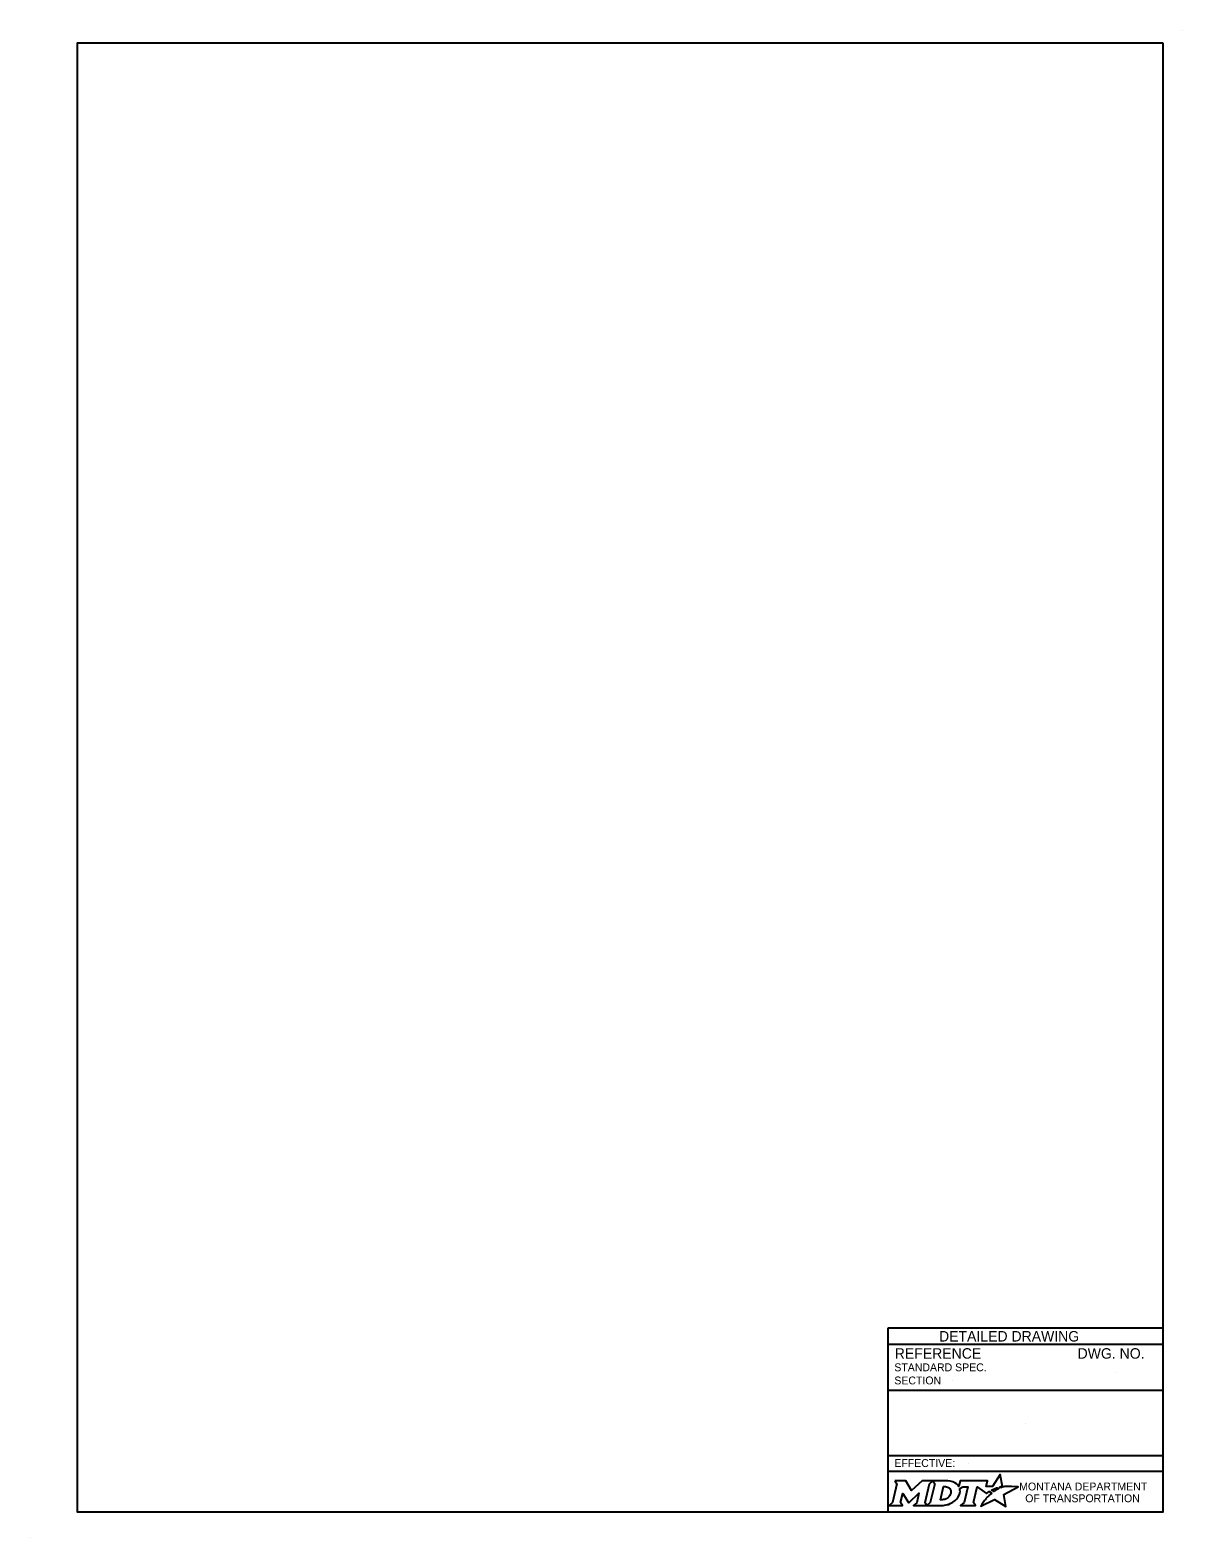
# Model space of a CAD drawing. Extents: x 49991.4 to 50021, y 49987.6 to 50011.4.
# Drawn here: x 49999.98 to 50008.76, y 49999.86 to 50011.36 of the extents above; entities that cross this region are included whole.
import ezdxf

# ---------------------------------------------------------------- set-up
doc = ezdxf.new("R2010")
doc.units = 0
doc.layers.add('Level 1', color=7, linetype='Continuous')
doc.layers.add('Level 2', color=7, linetype='Continuous')

msp = doc.modelspace()

# ---------------------------------------------------------------- linework, layer by layer
at = {"layer": 'Level 1'}
for p, q in [((50008.765, 50011.363), (50008.765, 50011.363)), ((49999.977, 49999.862), (49999.977, 49999.862))]:
    msp.add_line(p, q, dxfattribs=at)
msp.add_lwpolyline([(50008.615, 50011.263), (50000.336, 50011.263), (50000.336, 50000.062), (50008.615, 50000.062)], close=True, dxfattribs=at)
at = {"layer": 'Level 2'}
for p, q in [((50008.615, 50001.462), (50006.515, 50001.462)), ((50006.515, 50001.462), (50006.515, 50000.062)), ((50008.615, 50001.337), (50006.515, 50001.337)), ((50008.251, 50001.122), (50008.251, 50001.122)), ((50008.615, 50000.987), (50006.515, 50000.987)), ((50007.009, 50001.063), (50007.009, 50001.063)), ((50007.565, 50000.738), (50007.565, 50000.738)), ((50008.615, 50000.489), (50006.515, 50000.489)), ((50007.13, 50000.433), (50007.13, 50000.433)), ((50008.615, 50000.369), (50006.515, 50000.369))]:
    msp.add_line(p, q, dxfattribs=at)
for points in [[(50006.57, 50000.297), (50006.584, 50000.274), (50006.551, 50000.131), (50006.525, 50000.108), (50006.627, 50000.108), (50006.613, 50000.131), (50006.629, 50000.201), (50006.673, 50000.132), (50006.678, 50000.132), (50006.753, 50000.202), (50006.737, 50000.13), (50006.712, 50000.108), (50006.814, 50000.108), (50006.8, 50000.132), (50006.833, 50000.274)], [(50006.833, 50000.274), (50006.859, 50000.297), (50006.776, 50000.297), (50006.697, 50000.224), (50006.652, 50000.297), (50006.57, 50000.297)], [(50006.972, 50000.297), (50006.859, 50000.297), (50006.873, 50000.275), (50006.839, 50000.131), (50006.814, 50000.108), (50006.925, 50000.108)], [(50007.377, 50000.245), (50007.367, 50000.25), (50007.378, 50000.253), (50007.39, 50000.255), (50007.373, 50000.345), (50007.313, 50000.254), (50007.266, 50000.253), (50007.276, 50000.297), (50007.067, 50000.297), (50007.057, 50000.255), (50007.051, 50000.263)], [(50006.996, 50000.211), (50006.995, 50000.203), (50006.992, 50000.193), (50006.988, 50000.185), (50006.982, 50000.178), (50006.976, 50000.171), (50006.968, 50000.164), (50006.959, 50000.16), (50006.95, 50000.156), (50006.941, 50000.154), (50006.932, 50000.153), (50006.916, 50000.153), (50006.94, 50000.253), (50006.956, 50000.253), (50006.963, 50000.252), (50006.971, 50000.25), (50006.977, 50000.247), (50006.983, 50000.243), (50006.988, 50000.238), (50006.992, 50000.232), (50006.995, 50000.226), (50006.996, 50000.218), (50006.996, 50000.215), (50006.996, 50000.211)], [(50007.064, 50000.238), (50007.088, 50000.251), (50007.125, 50000.251), (50007.097, 50000.131), (50007.069, 50000.108), (50007.185, 50000.108), (50007.168, 50000.131), (50007.196, 50000.251), (50007.268, 50000.2), (50007.289, 50000.215), (50007.309, 50000.204)], [(50007.253, 50000.148), (50007.237, 50000.124), (50007.233, 50000.116), (50007.227, 50000.107), (50007.225, 50000.103), (50007.33, 50000.156), (50007.414, 50000.101), (50007.401, 50000.194), (50007.508, 50000.252), (50007.458, 50000.253), (50007.428, 50000.253), (50007.407, 50000.254), (50007.401, 50000.252), (50007.396, 50000.251), (50007.387, 50000.249), (50007.377, 50000.245)], [(50007.327, 50000.217), (50007.324, 50000.215), (50007.306, 50000.225), (50007.316, 50000.231), (50007.32, 50000.233), (50007.329, 50000.237), (50007.335, 50000.239), (50007.343, 50000.243), (50007.35, 50000.245), (50007.362, 50000.238), (50007.358, 50000.236), (50007.353, 50000.233), (50007.349, 50000.231), (50007.344, 50000.228), (50007.342, 50000.227), (50007.339, 50000.225), (50007.337, 50000.224), (50007.334, 50000.222), (50007.332, 50000.221), (50007.329, 50000.219), (50007.327, 50000.217)], [(50006.97, 50000.116), (50006.979, 50000.118), (50006.992, 50000.124), (50007.012, 50000.135)], [(50007.267, 50000.164), (50007.267, 50000.164)]]:
    msp.add_lwpolyline(points, dxfattribs=at)
for centre, radius, start, end in [((50006.951, 50000.236), 0.118, 300.9103, 339.1383), ((50006.995, 50000.219), 0.0709, 339.5329, 15.8582)]:
    msp.add_arc(centre, radius, start, end, dxfattribs=at)
for centre, major_axis, ratio, start_param, end_param in [((50006.97, 50000.25), (0.0834, -0.0037), 0.568097, 0.61298, 1.570796), ((50007.026, 50000.257), (0.0361, -0.0295), 0.469099, 1.225588, 1.570796), ((50007.276, 50000.174), (-0.0098, -0.0102), 0.016458, 3.141593, 6.279097), ((50007.297, 50000.194), (-0.0112, -0.0097), 0.021651, 3.157348, 6.283185), ((50006.925, 50000.257), (0, 0.148), 0.987302, 3.139398, 3.456847), ((50007.26, 50000.156), (-0.00694, -0.00806), 0.008222, 0, 3.137361)]:
    msp.add_ellipse(centre, major_axis=major_axis, ratio=ratio, start_param=start_param, end_param=end_param, dxfattribs=at)

# ---------------------------------------------------------------- texts
for s, height, p in [('DETAILED DRAWING', 0.0799, (50006.906, 50001.36)), ('REFERENCE', 0.08, (50006.568, 50001.229)), ('DWG. NO.', 0.08, (50007.962, 50001.229)), ('STANDARD SPEC.', 0.06, (50006.565, 50001.133)), ('SECTION', 0.06, (50006.565, 50001.033)), ('EFFECTIVE:', 0.06, (50006.565, 50000.403))]:
    msp.add_text(s, height=height, dxfattribs=at).set_placement(p)
for s, p in [('MONTANA DEPARTMENT', (50007.517, 50000.224)), ('OF TRANSPORTATION', (50007.563, 50000.134))]:
    msp.add_text(s, height=0.06, rotation=360, dxfattribs=at).set_placement(p)

doc.saveas('drawing.dxf')
